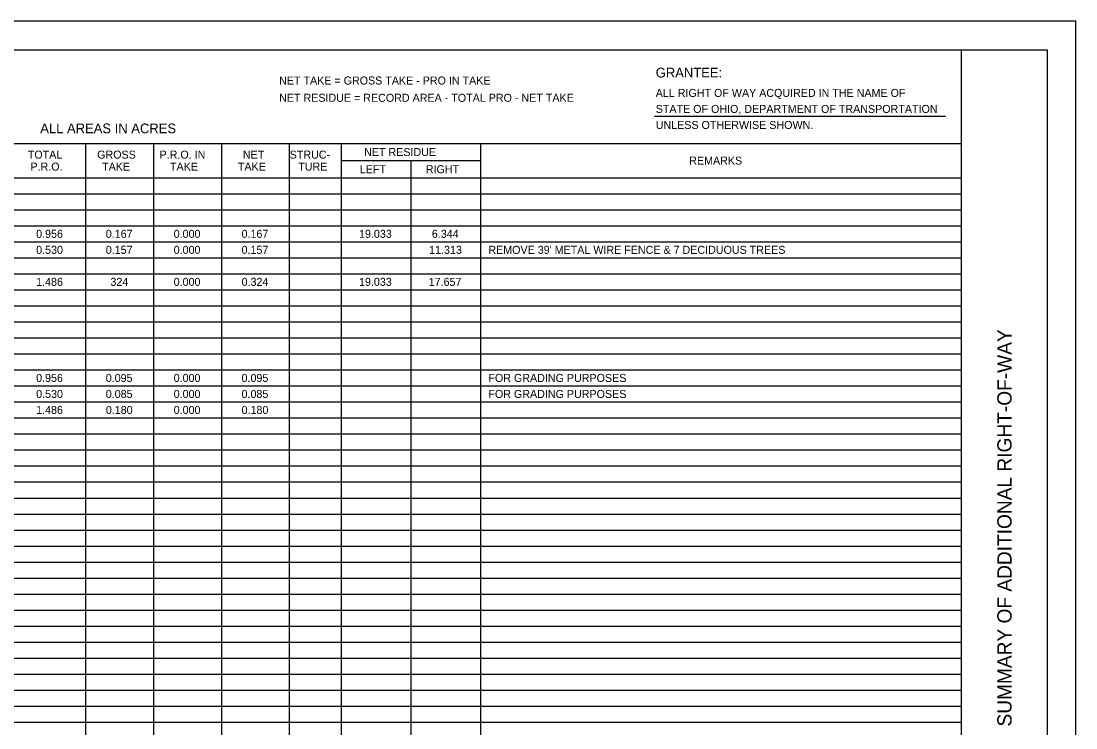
# Model space of a CAD drawing. Extents: x 0 to 34, y 0 to 22.
# Drawn here: x 15.55 to 34, y 9.64 to 22 of the extents above; entities that cross this region are included whole.
import ezdxf

# ---------------------------------------------------------------- set-up
doc = ezdxf.new("R2010")
doc.units = 0
for name, color, linetype in [('DV_X_Text', 7, 'Continuous'), ('SC_Scratch1', 7, 'Continuous'), ('SH_Border', 7, 'Continuous'), ('SH_Cut_Line', 7, 'Continuous'), ('SH_Data', 7, 'Continuous'), ('SH_Text', 7, 'Continuous')]:
    doc.layers.add(name, color=color, linetype=linetype)

msp = doc.modelspace()

# ---------------------------------------------------------------- linework, layer by layer
at = {"layer": 'SC_Scratch1'}
for p, q in [((16.052, 19.12), (16.052, 19.12)), ((17.271, 19.12), (17.271, 19.12)), ((18.458, 19.12), (18.458, 19.12)), ((19.646, 19.12), (19.646, 19.12)), ((20.692, 19.12), (20.692, 19.12)), ((21.755, 19.12), (21.755, 19.12)), ((22.974, 19.12), (22.974, 19.12)), ((23.723, 19.12), (23.723, 19.12)), ((16.052, 18.84), (16.052, 18.84)), ((17.271, 18.84), (17.271, 18.84)), ((18.458, 18.84), (18.458, 18.84)), ((19.646, 18.84), (19.646, 18.84)), ((20.692, 18.84), (20.692, 18.84)), ((21.755, 18.84), (21.755, 18.84)), ((22.974, 18.84), (22.974, 18.84)), ((23.723, 18.84), (23.723, 18.84)), ((16.052, 18.56), (16.052, 18.56)), ((17.271, 18.56), (17.271, 18.56)), ((18.458, 18.56), (18.458, 18.56)), ((19.646, 18.56), (19.646, 18.56)), ((20.692, 18.56), (20.692, 18.56)), ((21.755, 18.56), (21.755, 18.56)), ((22.974, 18.56), (22.974, 18.56)), ((23.723, 18.56), (23.723, 18.56)), ((16.052, 18.28), (16.052, 18.28)), ((17.271, 18.28), (17.271, 18.28)), ((18.458, 18.28), (18.458, 18.28)), ((19.646, 18.28), (19.646, 18.28)), ((20.692, 18.28), (20.692, 18.28)), ((21.755, 18.28), (21.755, 18.28)), ((22.974, 18.28), (22.974, 18.28)), ((23.723, 18.28), (23.723, 18.28)), ((16.052, 18), (16.052, 18)), ((17.271, 18), (17.271, 18)), ((18.458, 18), (18.458, 18)), ((19.646, 18), (19.646, 18)), ((20.692, 18), (20.692, 18)), ((21.755, 18), (21.755, 18)), ((22.974, 18), (22.974, 18)), ((23.723, 18), (23.723, 18)), ((16.052, 17.72), (16.052, 17.72)), ((17.271, 17.72), (17.271, 17.72)), ((18.458, 17.72), (18.458, 17.72)), ((19.646, 17.72), (19.646, 17.72)), ((20.692, 17.72), (20.692, 17.72)), ((21.755, 17.72), (21.755, 17.72)), ((22.974, 17.72), (22.974, 17.72)), ((23.723, 17.72), (23.723, 17.72)), ((16.052, 17.44), (16.052, 17.44)), ((17.271, 17.44), (17.271, 17.44)), ((18.458, 17.44), (18.458, 17.44)), ((19.646, 17.44), (19.646, 17.44)), ((20.692, 17.44), (20.692, 17.44)), ((21.755, 17.44), (21.755, 17.44)), ((22.974, 17.44), (22.974, 17.44)), ((23.723, 17.44), (23.723, 17.44)), ((16.052, 17.16), (16.052, 17.16)), ((17.271, 17.16), (17.271, 17.16)), ((18.458, 17.16), (18.458, 17.16)), ((19.646, 17.16), (19.646, 17.16)), ((20.692, 17.16), (20.692, 17.16)), ((21.755, 17.16), (21.755, 17.16)), ((22.974, 17.16), (22.974, 17.16)), ((23.723, 17.16), (23.723, 17.16)), ((16.052, 16.88), (16.052, 16.88)), ((17.271, 16.88), (17.271, 16.88)), ((18.458, 16.88), (18.458, 16.88)), ((19.646, 16.88), (19.646, 16.88)), ((20.692, 16.88), (20.692, 16.88)), ((21.755, 16.88), (21.755, 16.88)), ((22.974, 16.88), (22.974, 16.88)), ((23.723, 16.88), (23.723, 16.88)), ((16.052, 16.6), (16.052, 16.6)), ((17.271, 16.6), (17.271, 16.6)), ((18.458, 16.6), (18.458, 16.6)), ((19.646, 16.6), (19.646, 16.6)), ((20.692, 16.6), (20.692, 16.6)), ((21.755, 16.6), (21.755, 16.6)), ((22.974, 16.6), (22.974, 16.6)), ((23.723, 16.6), (23.723, 16.6)), ((16.052, 16.32), (16.052, 16.32)), ((17.271, 16.32), (17.271, 16.32)), ((18.458, 16.32), (18.458, 16.32)), ((19.646, 16.32), (19.646, 16.32)), ((20.692, 16.32), (20.692, 16.32)), ((21.755, 16.32), (21.755, 16.32)), ((22.974, 16.32), (22.974, 16.32)), ((23.723, 16.32), (23.723, 16.32)), ((16.052, 16.04), (16.052, 16.04)), ((17.271, 16.04), (17.271, 16.04)), ((18.458, 16.04), (18.458, 16.04)), ((19.646, 16.04), (19.646, 16.04)), ((20.692, 16.04), (20.692, 16.04)), ((21.755, 16.04), (21.755, 16.04)), ((22.974, 16.04), (22.974, 16.04)), ((23.723, 16.04), (23.723, 16.04)), ((16.052, 15.76), (16.052, 15.76)), ((17.271, 15.76), (17.271, 15.76)), ((18.458, 15.76), (18.458, 15.76)), ((19.646, 15.76), (19.646, 15.76)), ((20.692, 15.76), (20.692, 15.76)), ((21.755, 15.76), (21.755, 15.76)), ((22.974, 15.76), (22.974, 15.76)), ((23.723, 15.76), (23.723, 15.76)), ((16.052, 15.48), (16.052, 15.48)), ((17.271, 15.48), (17.271, 15.48)), ((18.458, 15.48), (18.458, 15.48)), ((19.646, 15.48), (19.646, 15.48)), ((20.692, 15.48), (20.692, 15.48)), ((21.755, 15.48), (21.755, 15.48)), ((22.974, 15.48), (22.974, 15.48)), ((23.723, 15.48), (23.723, 15.48)), ((16.052, 15.2), (16.052, 15.2)), ((17.271, 15.2), (17.271, 15.2)), ((18.458, 15.2), (18.458, 15.2)), ((19.646, 15.2), (19.646, 15.2)), ((20.692, 15.2), (20.692, 15.2)), ((21.755, 15.2), (21.755, 15.2)), ((22.974, 15.2), (22.974, 15.2)), ((23.723, 15.2), (23.723, 15.2)), ((16.052, 14.92), (16.052, 14.92)), ((17.271, 14.92), (17.271, 14.92)), ((18.458, 14.92), (18.458, 14.92)), ((19.646, 14.92), (19.646, 14.92)), ((20.692, 14.92), (20.692, 14.92)), ((21.755, 14.92), (21.755, 14.92)), ((22.974, 14.92), (22.974, 14.92)), ((23.723, 14.92), (23.723, 14.92)), ((16.052, 14.64), (16.052, 14.64)), ((17.271, 14.64), (17.271, 14.64)), ((18.458, 14.64), (18.458, 14.64)), ((19.646, 14.64), (19.646, 14.64)), ((20.692, 14.64), (20.692, 14.64)), ((21.755, 14.64), (21.755, 14.64)), ((22.974, 14.64), (22.974, 14.64)), ((23.723, 14.64), (23.723, 14.64)), ((16.052, 14.36), (16.052, 14.36)), ((17.271, 14.36), (17.271, 14.36)), ((18.458, 14.36), (18.458, 14.36)), ((19.646, 14.36), (19.646, 14.36)), ((20.692, 14.36), (20.692, 14.36)), ((21.755, 14.36), (21.755, 14.36)), ((22.974, 14.36), (22.974, 14.36)), ((23.723, 14.36), (23.723, 14.36)), ((16.052, 14.08), (16.052, 14.08)), ((17.271, 14.08), (17.271, 14.08)), ((18.458, 14.08), (18.458, 14.08)), ((19.646, 14.08), (19.646, 14.08)), ((20.692, 14.08), (20.692, 14.08)), ((21.755, 14.08), (21.755, 14.08)), ((22.974, 14.08), (22.974, 14.08)), ((23.723, 14.08), (23.723, 14.08)), ((16.052, 13.8), (16.052, 13.8)), ((17.271, 13.8), (17.271, 13.8)), ((18.458, 13.8), (18.458, 13.8)), ((19.646, 13.8), (19.646, 13.8)), ((20.692, 13.8), (20.692, 13.8)), ((21.755, 13.8), (21.755, 13.8)), ((22.974, 13.8), (22.974, 13.8)), ((23.723, 13.8), (23.723, 13.8)), ((16.052, 13.52), (16.052, 13.52)), ((17.271, 13.52), (17.271, 13.52)), ((18.458, 13.52), (18.458, 13.52)), ((19.646, 13.52), (19.646, 13.52)), ((20.692, 13.52), (20.692, 13.52)), ((21.755, 13.52), (21.755, 13.52)), ((22.974, 13.52), (22.974, 13.52)), ((23.723, 13.52), (23.723, 13.52)), ((16.052, 13.24), (16.052, 13.24)), ((17.271, 13.24), (17.271, 13.24)), ((18.458, 13.24), (18.458, 13.24)), ((19.646, 13.24), (19.646, 13.24)), ((20.692, 13.24), (20.692, 13.24)), ((21.755, 13.24), (21.755, 13.24)), ((22.974, 13.24), (22.974, 13.24)), ((23.723, 13.24), (23.723, 13.24)), ((16.052, 12.96), (16.052, 12.96)), ((17.271, 12.96), (17.271, 12.96)), ((18.458, 12.96), (18.458, 12.96)), ((19.646, 12.96), (19.646, 12.96)), ((20.692, 12.96), (20.692, 12.96)), ((21.755, 12.96), (21.755, 12.96)), ((22.974, 12.96), (22.974, 12.96)), ((23.723, 12.96), (23.723, 12.96)), ((16.052, 12.68), (16.052, 12.68)), ((17.271, 12.68), (17.271, 12.68)), ((18.458, 12.68), (18.458, 12.68)), ((19.646, 12.68), (19.646, 12.68)), ((20.692, 12.68), (20.692, 12.68)), ((21.755, 12.68), (21.755, 12.68)), ((22.974, 12.68), (22.974, 12.68)), ((23.723, 12.68), (23.723, 12.68)), ((16.052, 12.4), (16.052, 12.4)), ((17.271, 12.4), (17.271, 12.4)), ((18.458, 12.4), (18.458, 12.4)), ((19.646, 12.4), (19.646, 12.4)), ((20.692, 12.4), (20.692, 12.4)), ((21.755, 12.4), (21.755, 12.4)), ((22.974, 12.4), (22.974, 12.4)), ((23.723, 12.4), (23.723, 12.4)), ((16.052, 12.12), (16.052, 12.12)), ((17.271, 12.12), (17.271, 12.12)), ((18.458, 12.12), (18.458, 12.12)), ((19.646, 12.12), (19.646, 12.12)), ((20.692, 12.12), (20.692, 12.12)), ((21.755, 12.12), (21.755, 12.12)), ((22.974, 12.12), (22.974, 12.12)), ((23.723, 12.12), (23.723, 12.12)), ((16.052, 11.84), (16.052, 11.84)), ((17.271, 11.84), (17.271, 11.84)), ((18.458, 11.84), (18.458, 11.84)), ((19.646, 11.84), (19.646, 11.84)), ((20.692, 11.84), (20.692, 11.84)), ((21.755, 11.84), (21.755, 11.84)), ((22.974, 11.84), (22.974, 11.84)), ((23.723, 11.84), (23.723, 11.84)), ((16.052, 11.56), (16.052, 11.56)), ((17.271, 11.56), (17.271, 11.56)), ((18.458, 11.56), (18.458, 11.56)), ((19.646, 11.56), (19.646, 11.56)), ((20.692, 11.56), (20.692, 11.56)), ((21.755, 11.56), (21.755, 11.56)), ((22.974, 11.56), (22.974, 11.56)), ((23.723, 11.56), (23.723, 11.56)), ((16.052, 11.28), (16.052, 11.28)), ((17.271, 11.28), (17.271, 11.28)), ((18.458, 11.28), (18.458, 11.28)), ((19.646, 11.28), (19.646, 11.28)), ((20.692, 11.28), (20.692, 11.28)), ((21.755, 11.28), (21.755, 11.28)), ((22.974, 11.28), (22.974, 11.28)), ((23.723, 11.28), (23.723, 11.28)), ((16.052, 11), (16.052, 11)), ((17.271, 11), (17.271, 11)), ((18.458, 11), (18.458, 11)), ((19.646, 11), (19.646, 11)), ((20.692, 11), (20.692, 11)), ((21.755, 11), (21.755, 11)), ((22.974, 11), (22.974, 11)), ((23.723, 11), (23.723, 11)), ((16.052, 10.72), (16.052, 10.72)), ((17.271, 10.72), (17.271, 10.72)), ((18.458, 10.72), (18.458, 10.72)), ((19.646, 10.72), (19.646, 10.72)), ((20.692, 10.72), (20.692, 10.72)), ((21.755, 10.72), (21.755, 10.72)), ((22.974, 10.72), (22.974, 10.72)), ((23.723, 10.72), (23.723, 10.72)), ((16.052, 10.44), (16.052, 10.44)), ((17.271, 10.44), (17.271, 10.44)), ((18.458, 10.44), (18.458, 10.44)), ((19.646, 10.44), (19.646, 10.44)), ((20.692, 10.44), (20.692, 10.44)), ((21.755, 10.44), (21.755, 10.44)), ((22.974, 10.44), (22.974, 10.44)), ((23.723, 10.44), (23.723, 10.44)), ((16.052, 10.16), (16.052, 10.16)), ((17.271, 10.16), (17.271, 10.16)), ((18.458, 10.16), (18.458, 10.16)), ((19.646, 10.16), (19.646, 10.16)), ((20.692, 10.16), (20.692, 10.16)), ((21.755, 10.16), (21.755, 10.16)), ((22.974, 10.16), (22.974, 10.16)), ((23.723, 10.16), (23.723, 10.16)), ((16.052, 9.88), (16.052, 9.88)), ((17.271, 9.88), (17.271, 9.88)), ((18.458, 9.88), (18.458, 9.88)), ((19.646, 9.88), (19.646, 9.88)), ((20.692, 9.88), (20.692, 9.88)), ((21.755, 9.88), (21.755, 9.88)), ((22.974, 9.88), (22.974, 9.88)), ((23.723, 9.88), (23.723, 9.88))]:
    msp.add_line(p, q, dxfattribs=at)
at = {"layer": 'SH_Border'}
msp.add_line((32, 0.5), (32, 21.5), dxfattribs=at)
msp.add_lwpolyline([(1.5, 21.5), (33.5, 21.5), (33.5, 0.5), (1.5, 0.5)], close=True, dxfattribs=at)
at = {"layer": 'SH_Cut_Line'}
msp.add_lwpolyline([(0, 0), (34, 0), (34, 22), (0, 22)], close=True, dxfattribs=at)
at = {"layer": 'SH_Data'}
for p, q in [((1.5, 19.86), (32, 19.86)), ((16.677, 19.86), (16.677, 3.02)), ((17.864, 19.86), (17.864, 3.02)), ((19.052, 19.86), (19.052, 3.02)), ((20.239, 19.86), (20.239, 3.02)), ((21.146, 19.86), (21.146, 3.02)), ((23.583, 19.86), (23.583, 3.02)), ((21.146, 19.56), (23.583, 19.56)), ((22.364, 19.56), (22.364, 3.02)), ((1.5, 19.26), (32, 19.26)), ((1.5, 18.98), (32, 18.98)), ((1.5, 18.7), (32, 18.7)), ((1.5, 18.42), (32, 18.42)), ((1.5, 18.14), (32, 18.14)), ((1.5, 17.86), (32, 17.86)), ((1.5, 17.58), (32, 17.58)), ((1.5, 17.3), (32, 17.3)), ((1.5, 17.02), (32, 17.02)), ((1.5, 16.74), (32, 16.74)), ((1.5, 16.46), (32, 16.46)), ((1.5, 16.18), (32, 16.18)), ((1.5, 15.9), (32, 15.9)), ((1.5, 15.62), (32, 15.62)), ((1.5, 15.34), (32, 15.34)), ((1.5, 15.06), (32, 15.06)), ((1.5, 14.78), (32, 14.78)), ((1.5, 14.5), (32, 14.5)), ((1.5, 14.22), (32, 14.22)), ((1.5, 13.94), (32, 13.94)), ((1.5, 13.66), (32, 13.66)), ((1.5, 13.38), (32, 13.38)), ((1.5, 13.1), (32, 13.1)), ((1.5, 12.82), (32, 12.82)), ((1.5, 12.54), (32, 12.54)), ((1.5, 12.26), (32, 12.26)), ((1.5, 11.98), (32, 11.98)), ((1.5, 11.7), (32, 11.7)), ((1.5, 11.42), (32, 11.42)), ((1.5, 11.14), (32, 11.14)), ((1.5, 10.86), (32, 10.86)), ((1.5, 10.58), (32, 10.58)), ((1.5, 10.3), (32, 10.3)), ((1.5, 10.02), (32, 10.02)), ((1.5, 9.74), (32, 9.74))]:
    msp.add_line(p, q, dxfattribs=at)
at = {"layer": 'SH_Text'}
msp.add_line((26.628, 20.337), (31.717, 20.337), dxfattribs=at)

# ---------------------------------------------------------------- texts
at = {"layer": 'DV_X_Text'}
for s, p in [('0.956', (15.812, 18.21)), ('0.167', (17.03, 18.21)), ('0.000', (18.218, 18.21)), ('0.167', (19.405, 18.21)), ('19.033', (21.46, 18.21)), ('6.344', (22.734, 18.21)), ('0.530', (15.812, 17.93)), ('0.157', (17.03, 17.93)), ('0.000', (18.218, 17.93)), ('0.157', (19.405, 17.93)), ('11.313', (22.686, 17.93)), ("REMOVE 39' METAL WIRE FENCE & 7 DECIDUOUS TREES", (23.723, 17.93)), ('1.486', (15.812, 17.37)), ('324', (17.112, 17.37)), ('0.000', (18.218, 17.37)), ('0.324', (19.406, 17.37)), ('19.033', (21.46, 17.37)), ('17.657', (22.679, 17.37)), ('0.956', (15.812, 15.69)), ('0.095', (17.03, 15.69)), ('0.000', (18.218, 15.69)), ('0.095', (19.405, 15.69)), ('FOR GRADING PURPOSES', (23.723, 15.69)), ('0.530', (15.812, 15.41)), ('0.085', (17.03, 15.41)), ('0.000', (18.218, 15.41)), ('0.085', (19.405, 15.41)), ('FOR GRADING PURPOSES', (23.723, 15.41)), ('1.486', (15.812, 15.13)), ('0.180', (17.031, 15.13)), ('0.000', (18.218, 15.13)), ('0.180', (19.406, 15.13))]:
    msp.add_text(s, height=0.14, dxfattribs=at).set_placement(p)
at = {"layer": 'SH_Data'}
for s, height, rotation, p in [('ALL AREAS IN ACRES', 0.17, 360, (15.884, 20.039)), ('NET RESIDUE', 0.14, 360, (21.549, 19.64)), ('TOTAL', 0.14, 360, (15.666, 19.595)), ('GROSS', 0.14, 360, (16.879, 19.595)), ('P.R.O. IN', 0.14, 360, (17.971, 19.595)), ('NET', 0.14, 360, (19.428, 19.595)), ('STRUC-', 0.14, 360, (20.247, 19.595)), ('REMARKS', 0.14, 360, (27.236, 19.49)), ('P.R.O.', 0.14, 360, (15.712, 19.385)), ('TAKE', 0.14, 360, (16.966, 19.385)), ('TAKE', 0.14, 360, (18.154, 19.385)), ('TAKE', 0.14, 360, (19.341, 19.385)), ('TURE', 0.14, 360, (20.397, 19.385)), ('LEFT', 0.14, 360, (21.473, 19.34)), ('RIGHT', 0.14, 360, (22.628, 19.34)), ('SUMMARY OF ADDITIONAL RIGHT-OF-WAY', 0.25, 90, (32.875, 9.664))]:
    msp.add_text(s, height=height, rotation=rotation, dxfattribs=at).set_placement(p)
at = {"layer": 'SH_Text'}
for s, height, p in [('GRANTEE:', 0.17, (26.65, 21.014)), ('NET TAKE = GROSS TAKE - PRO IN TAKE', 0.14, (20.062, 20.891)), ('NET RESIDUE = RECORD AREA - TOTAL PRO - NET TAKE', 0.14, (20.062, 20.589)), ('ALL RIGHT OF WAY ACQUIRED IN THE NAME OF', 0.14, (26.65, 20.674)), ('STATE OF OHIO, DEPARTMENT OF TRANSPORTATION', 0.14, (26.65, 20.394)), ('UNLESS OTHERWISE SHOWN.', 0.14, (26.65, 20.114))]:
    msp.add_text(s, height=height, dxfattribs=at).set_placement(p)

doc.saveas('drawing.dxf')
